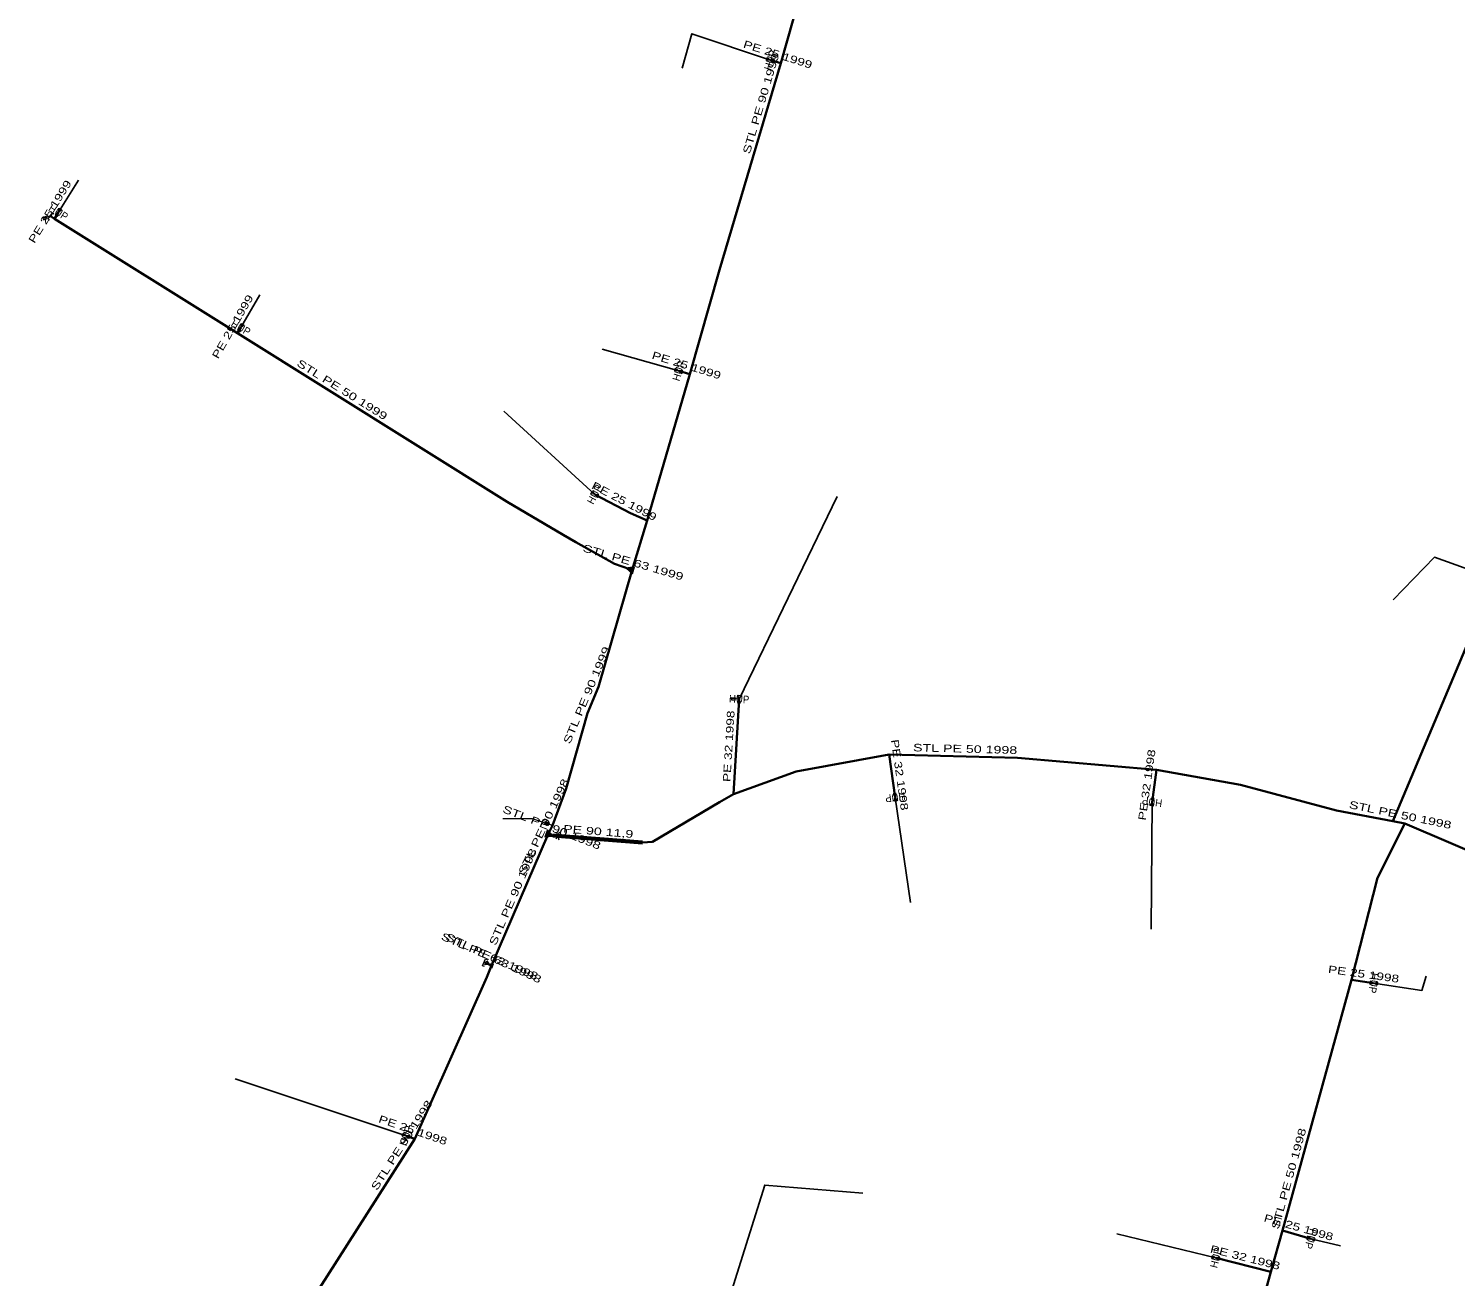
# Model space of a CAD drawing. Extents: x -737484 to -734496, y -1033882 to -1030666.
# Drawn here: x -735937.2 to -735749, y -1031903.6 to -1031739 of the extents above; entities that cross this region are included whole.
import ezdxf
from ezdxf.enums import TextEntityAlignment as Align

# ---------------------------------------------------------------- set-up
doc = ezdxf.new("R2010")
doc.units = 0
doc.header["$LTSCALE"] = 0.4
for name, color, linetype, lineweight in [('1', 7, 'Continuous', 13), ('18', 7, 'Continuous', 60), ('22', 7, 'Continuous', 25), ('5', 7, 'Continuous', 35), ('7', 7, 'Continuous', 35)]:
    doc.layers.add(name, color=color, linetype=linetype, lineweight=lineweight)
doc.layers.add('2', color=7, linetype='Continuous')

msp = doc.modelspace()

# ---------------------------------------------------------------- linework, layer by layer
at = {"layer": '1'}
for p, q in [((-735934.896, -1031763.884), (-735935.218, -1031764.021)), ((-735934.338, -1031763.729), (-735934.798, -1031763.924)), ((-735844.04, -1031827.345), (-735844.389, -1031827.326)), ((-735843.47, -1031827.45), (-735843.969, -1031827.423)), ((-735868.603, -1031843.822), (-735868.932, -1031843.703)), ((-735868.089, -1031844.09), (-735868.558, -1031843.918)), ((-735867.149, -1031844.988), (-735867.668, -1031845.931)), ((-735867.546, -1031844.939), (-735867.271, -1031845.98))]:
    msp.add_line(p, q, dxfattribs=at)
for points in [[(-735839.883, -1031743.235), (-735839.766, -1031742.852), (-735838.927, -1031743.527), (-735838.81, -1031743.144)], [(-735935.258, -1031764.119), (-735935.317, -1031763.981), (-735934.856, -1031763.786), (-735934.798, -1031763.924)], [(-735935.237, -1031764.07), (-735935.267, -1031764.001), (-735934.876, -1031763.835), (-735934.846, -1031763.904)], [(-735935.258, -1031764.119), (-735935.199, -1031764.257), (-735934.739, -1031764.062), (-735934.798, -1031763.924)], [(-735933.163, -1031762.729), (-735932.824, -1031762.941), (-735933.693, -1031763.578), (-735933.354, -1031763.79)], [(-735909.123, -1031777.935), (-735908.776, -1031778.135), (-735909.623, -1031778.802), (-735909.276, -1031779.002)], [(-735851.974, -1031784.214), (-735851.857, -1031783.831), (-735851.018, -1031784.506), (-735850.901, -1031784.123)], [(-735863.053, -1031800.389), (-735862.865, -1031800.036), (-735862.17, -1031800.859), (-735861.982, -1031800.506)], [(-735857.534, -1031810.945), (-735857.258, -1031809.984), (-735858.357, -1031810.189)], [(-735857.399, -1031810.112), (-735858.142, -1031810.25), (-735857.585, -1031810.762)], [(-735857.927, -1031810.312), (-735857.637, -1031810.578), (-735857.539, -1031810.239)], [(-735844.468, -1031827.397), (-735844.476, -1031827.547), (-735843.977, -1031827.573), (-735843.969, -1031827.423)], [(-735844.468, -1031827.397), (-735844.46, -1031827.247), (-735843.961, -1031827.274), (-735843.969, -1031827.423)], [(-735844.428, -1031827.362), (-735844.424, -1031827.287), (-735844, -1031827.31), (-735844.004, -1031827.384)], [(-735843.64, -1031826.939), (-735843.241, -1031826.96), (-735843.692, -1031827.937), (-735843.293, -1031827.958)], [(-735822.61, -1031840.866), (-735823.006, -1031840.921), (-735822.749, -1031839.876), (-735823.145, -1031839.931)], [(-735788.871, -1031841.54), (-735789.267, -1031841.485), (-735788.732, -1031840.55), (-735789.128, -1031840.495)], [(-735869.028, -1031843.747), (-735868.977, -1031843.607), (-735868.507, -1031843.778), (-735868.558, -1031843.918)], [(-735868.747, -1031844.684), (-735869.105, -1031845.617), (-735867.993, -1031845.509)], [(-735869.028, -1031843.747), (-735869.079, -1031843.888), (-735868.61, -1031844.059), (-735868.558, -1031843.918)], [(-735868.98, -1031843.726), (-735868.954, -1031843.655), (-735868.555, -1031843.801), (-735868.58, -1031843.871)], [(-735868.954, -1031845.502), (-735868.202, -1031845.428), (-735868.712, -1031844.871)], [(-735868.41, -1031845.348), (-735868.677, -1031845.058), (-735868.803, -1031845.387)], [(-735877.009, -1031862.49), (-735876.756, -1031861.946), (-735876.103, -1031862.913), (-735875.85, -1031862.369)], [(-735759.255, -1031864.758), (-735759.31, -1031865.154), (-735760.245, -1031864.619), (-735760.3, -1031865.015)], [(-735887.935, -1031885.043), (-735887.805, -1031884.665), (-735886.99, -1031885.368), (-735886.86, -1031884.99)], [(-735767.531, -1031898.544), (-735767.641, -1031898.929), (-735768.492, -1031898.268), (-735768.602, -1031898.653)], [(-735781.111, -1031901.182), (-735781.014, -1031900.793), (-735780.141, -1031901.424), (-735780.044, -1031901.035)]]:
    msp.add_lwpolyline(points, close=True, dxfattribs=at)
for points in [[(-735934.42, -1031764.28), (-735934.624, -1031764.137), (-735934.051, -1031763.318), (-735933.846, -1031763.461)], [(-735868.09, -1031844.09), (-735870.732, -1031843.22), (-735874.66, -1031843.22)], [(-735877.074, -1031862.695), (-735877.304, -1031862.598), (-735876.913, -1031861.677), (-735876.683, -1031861.775)]]:
    msp.add_lwpolyline(points, dxfattribs=at)
at = {"layer": '18'}
msp.add_line((-735868.049, -1031845.41), (-735856.22, -1031846.359), dxfattribs=at)
at = {"layer": '22'}
for p, q in [((-735933.259, -1031763.26), (-735930.632, -1031759.006)), ((-735909.2, -1031778.469), (-735906.709, -1031774.134)), ((-735851.439, -1031784.17), (-735861.52, -1031781.289)), ((-735862.518, -1031800.448), (-735874.529, -1031789.489)), ((-735843.468, -1031827.449), (-735830.553, -1031800.721)), ((-735822.878, -1031840.399), (-735820.861, -1031854.245)), ((-735789, -1031841.018), (-735789.105, -1031857.773)), ((-735887.398, -1031885.017), (-735909.927, -1031877.492)), ((-735780.579, -1031901.109), (-735793.668, -1031897.94)), ((-735768.068, -1031898.599), (-735764.13, -1031899.52))]:
    msp.add_line(p, q, dxfattribs=at)
for points in [[(-735839.348, -1031743.19), (-735849.732, -1031739.72), (-735850.986, -1031744.237)], [(-735745.038, -1031811.159), (-735751.733, -1031808.741), (-735757.205, -1031814.361)], [(-735759.778, -1031864.888), (-735753.426, -1031865.871), (-735752.859, -1031863.968)], [(-735848.84, -1031919.359), (-735840.097, -1031891.524), (-735827.134, -1031892.578)]]:
    msp.add_lwpolyline(points, dxfattribs=at)
at = {"layer": '5'}
for p, q in [((-735857.56, -1031810.42), (-735857.877, -1031810.327)), ((-735757.24, -1031843.52), (-735755.68, -1031843.84)), ((-735868.64, -1031845.26), (-735868.09, -1031844.09)), ((-735876.43, -1031862.43), (-735877.109, -1031862.138)), ((-735876.13, -1031862.57), (-735876.43, -1031862.43))]:
    msp.add_line(p, q, dxfattribs=at)
for points in [[(-735857.56, -1031810.42), (-735855.59, -1031803.9), (-735849.97, -1031784.62), (-735846.04, -1031770.83), (-735837.98, -1031743.62), (-735832.95, -1031725.9), (-735827.48, -1031706.52), (-735821.67, -1031688)], [(-735757.24, -1031843.52), (-735745.19, -1031814.93), (-735743.54, -1031811.71), (-735736.86, -1031795.57), (-735725.69, -1031770.11), (-735724.59, -1031767.7), (-735719.92, -1031755.37), (-735712.74, -1031736.93), (-735708.84, -1031727.49), (-735749.83, -1031710.16), (-735750.469, -1031709.879)], [(-735857.877, -1031810.327), (-735859.91, -1031809.61), (-735864.99, -1031806.75), (-735866.68, -1031805.77), (-735874.07, -1031801.45), (-735909.62, -1031779.2), (-735933.79, -1031764.12), (-735934.338, -1031763.728)], [(-735868.09, -1031844.09), (-735866.29, -1031839.22), (-735863.49, -1031829.28), (-735862.04, -1031825.84), (-735857.56, -1031810.42)], [(-735868.46, -1031845.33), (-735868.05, -1031845.41), (-735867.41, -1031845.46), (-735856.22, -1031846.36), (-735854.92, -1031846.26), (-735846.08, -1031841.03), (-735844.221, -1031839.993), (-735835.97, -1031836.98), (-735823.68, -1031834.75), (-735806.74, -1031835.18), (-735788.4, -1031836.76), (-735777.34, -1031838.74), (-735764.66, -1031842.12), (-735757.24, -1031843.52)], [(-735876.13, -1031862.57), (-735868.64, -1031845.26), (-735868.46, -1031845.33)], [(-735755.68, -1031843.84), (-735759.27, -1031851), (-735762.69, -1031864.48), (-735771.82, -1031897.52), (-735773.35, -1031902.95), (-735774.59, -1031907.44), (-735782.3, -1031938.74)], [(-735755.68, -1031843.84), (-735738.06, -1031851.34), (-735723.63, -1031858.43), (-735717.56, -1031861.24), (-735713.84, -1031861.1), (-735707.27, -1031864.84), (-735702.03, -1031868.42), (-735698.48, -1031871.58), (-735695.52, -1031875.49), (-735676.258, -1031899.628)], [(-735901.44, -1031909.26), (-735886.25, -1031885.41), (-735876.77, -1031864.1), (-735876.13, -1031862.57)]]:
    msp.add_lwpolyline(points, dxfattribs=at)
at = {"layer": '7'}
for p, q in [((-735837.98, -1031743.62), (-735839.347, -1031743.19)), ((-735933.79, -1031764.12), (-735933.259, -1031763.26)), ((-735909.62, -1031779.2), (-735909.2, -1031778.469)), ((-735849.97, -1031784.62), (-735851.438, -1031784.169)), ((-735844.221, -1031839.993), (-735843.467, -1031827.449)), ((-735823.68, -1031834.75), (-735822.878, -1031840.399)), ((-735788.4, -1031836.76), (-735789, -1031841.018)), ((-735762.69, -1031864.48), (-735759.778, -1031864.887)), ((-735886.25, -1031885.41), (-735887.398, -1031885.017)), ((-735771.82, -1031897.52), (-735768.067, -1031898.599)), ((-735773.35, -1031902.95), (-735780.578, -1031901.109))]:
    msp.add_line(p, q, dxfattribs=at)
msp.add_lwpolyline([(-735855.59, -1031803.9), (-735857.79, -1031802.93), (-735862.518, -1031800.448)], dxfattribs=at)

# ---------------------------------------------------------------- texts
at = {"layer": '18', "width": 1.4}
msp.add_text('PE 90 11,9', height=1, rotation=355.413, dxfattribs=at).set_placement((-735862.094, -1031845.3858), align=Align.CENTER)
at = {"layer": '2', "width": 0.95}
for rotation, p in [(73, (-735838.8682, -1031743.3357)), (328, (-735933.5235, -1031763.6833)), (330, (-735909.4495, -1031778.9011)), (73, (-735850.9592, -1031784.3147)), (62, (-735862.076, -1031800.6822)), (357, (-735843.4927, -1031827.9475)), (188, (-735822.9469, -1031839.9037)), (172, (-735788.9299, -1031840.5223)), (262, (-735760.2727, -1031864.8169)), (71, (-735886.925, -1031885.1793)), (254, (-735768.5468, -1031898.4607)), (76, (-735780.092, -1031901.2295))]:
    msp.add_text('HUP', height=1, rotation=rotation, dxfattribs=at).set_placement(p, align=Align.CENTER)
at = {"layer": '5', "width": 1.4}
for s, rotation, p in [('STL PE 90 1999', 73.5, (-735840.1124, -1031749.06)), ('STL PE 50 1999', 327.958, (-735896.0983, -1031787.0716)), ('STL PE 63 1999', 343.65, (-735857.5773, -1031809.8935)), ('STL PE 90 1999', 67.144, (-735863.1202, -1031827.1172)), ('STL PE 50 1998', 358.546, (-735813.6707, -1031834.5031)), ('STL PE 90 1998', 64.822, (-735868.8175, -1031844.4617)), ('STL PE 90 1998', 338.749, (-735868.3682, -1031844.8285)), ('STL PE 50 1998', 348.408, (-735756.359, -1031843.1901)), ('STL PE 90 1998', 66.602, (-735872.8435, -1031853.7161)), ('STL PE 63 1998', 336.73, (-735876.5715, -1031861.8238)), ('STL PE 63 1998', 334.983, (-735876.0679, -1031862.0466)), ('STL PE 90 1998', 57.507, (-735887.5561, -1031886.5306)), ('STL PE 50 1998', 74.553, (-735770.4824, -1031890.8032))]:
    msp.add_text(s, height=1, rotation=rotation, dxfattribs=at).set_placement(p, align=Align.CENTER)
at = {"layer": '7', "width": 1.35}
for s, rotation, p in [('PE 25 1999', 342.539, (-735838.513, -1031742.928)), ('PE 25 1999', 58.307, (-735933.9498, -1031763.4267)), ('PE 25 1999', 60.12, (-735909.8433, -1031778.5851)), ('PE 25 1999', 342.922, (-735850.5568, -1031783.9163)), ('PE 25 1999', 332.302, (-735858.8569, -1031801.8046)), ('PE 32 1998', 86.56, (-735844.3431, -1031833.6905)), ('PE 32 1998', 278.08, (-735822.7835, -1031837.5032)), ('PE 32 1998', 81.979, (-735789.1944, -1031838.8188)), ('PE 25 1998', 352.044, (-735761.1642, -1031864.1883)), ('PE 25 1998', 341.102, (-735886.6614, -1031884.7404)), ('PE 25 1998', 343.96, (-735769.8047, -1031897.5781)), ('PE 32 1998', 345.71, (-735776.8404, -1031901.5445))]:
    msp.add_text(s, height=1, rotation=rotation, dxfattribs=at).set_placement(p, align=Align.CENTER)

doc.saveas('drawing.dxf')
